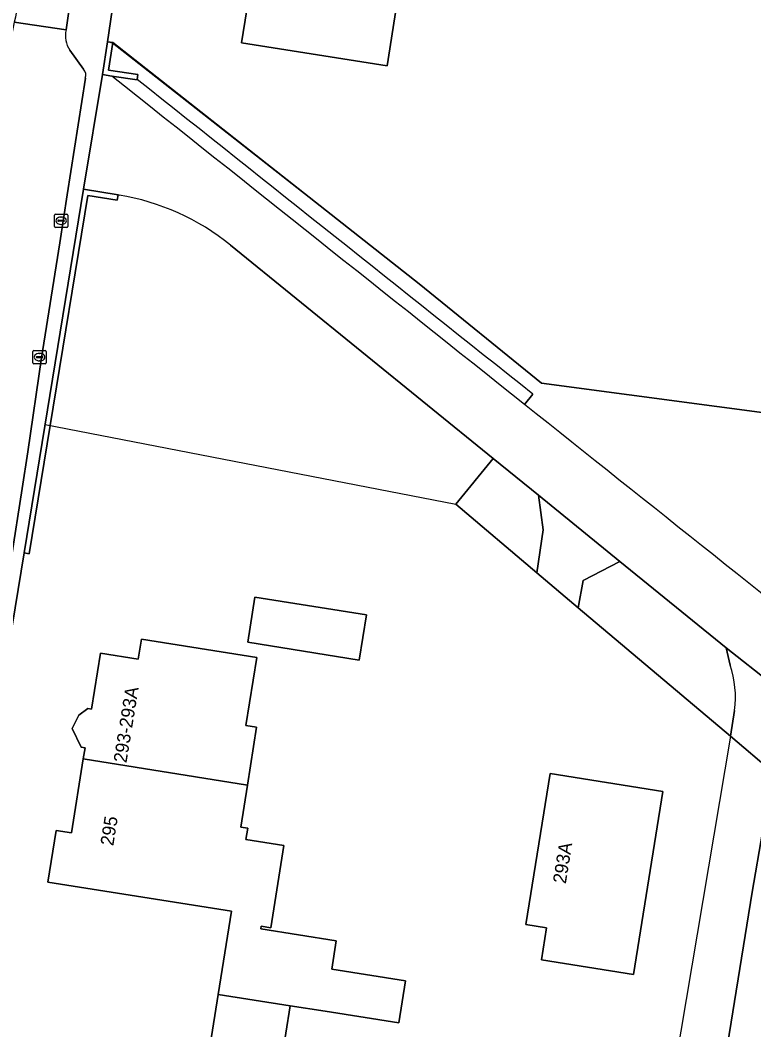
# Model space of a CAD drawing. Extents: x 161483 to 162250, y 379484 to 380833.
# Drawn here: x 161643 to 161698.5, y 380331.9 to 380408.4 of the extents above; entities that cross this region are included whole.
import ezdxf

# ---------------------------------------------------------------- set-up
doc = ezdxf.new("R2010")
doc.units = 0
for name, color, linetype in [('IMGEO_Berm_open', 7, 'Continuous'), ('IMGEO_Erf', 7, 'Continuous'), ('IMGEO_Gemengd_bos', 7, 'Continuous'), ('IMGEO_Groenvoorziening', 7, 'Continuous'), ('IMGEO_Hek', 7, 'Continuous'), ('IMGEO_Kolk', 7, 'Continuous'), ('IMGEO_Muur', 7, 'Continuous'), ('IMGEO_Pand', 7, 'Continuous'), ('IMGEO_Pand_nummerreeks', 7, 'Continuous'), ('IMGEO_Rijbaan_lokaal_gesloten', 7, 'Continuous'), ('IMGEO_Rijbaan_lokaal_open', 7, 'Continuous'), ('IMGEO_Voetpad_open', 7, 'Continuous')]:
    doc.layers.add(name, color=color, linetype=linetype)

msp = doc.modelspace()

# ---------------------------------------------------------------- linework, layer by layer
at = {"layer": 'IMGEO_Berm_open'}
for points in [[(161651.858, 380403.89), (161651.854, 380403.861), (161649.925, 380404.15)], [(161681.166, 380379.288), (161681.796, 380380.064)]]:
    msp.add_lwpolyline(points, dxfattribs=at)
for centre, radius, start, end in [((138294.945, 351024.776), 37531.357, 51.4562869, 51.517239), ((138866.822, 351743.167), 36614.135, 51.4557191, 51.5155932)]:
    msp.add_arc(centre, radius, start, end, dxfattribs=at)
at = {"layer": 'IMGEO_Erf'}
for points in [[(161655.481, 380444.917), (161652.656, 380427.511), (161649.605, 380406.735), (161650.001, 380406.676), (161673.199, 380388.404), (161682.464, 380380.888), (161735.153, 380373.873), (161748.237, 380371.945), (161806.448, 380361.939)], [(161650.485, 380395.132), (161650.417, 380395.143), (161650.352, 380394.748), (161648.132, 380395.111), (161645.281, 380377.689), (161643.693, 380367.982), (161643.298, 380368.047), (161641.71, 380358.328), (161639.778, 380345.223), (161639.349, 380342.516), (161637.808, 380332.784), (161635.369, 380317.381), (161635.308, 380316.997), (161633.936, 380308.445), (161631.258, 380291.759), (161630.498, 380287.027), (161630.411, 380286.482), (161629.564, 380286.608), (161620.762, 380287.923), (161620.152, 380288.014)], [(161689.432, 380260.789), (161685.342, 380261.452), (161698.403, 380342.353), (161699.96, 380351.452), (161696.758, 380354.158), (161685.238, 380363.892), (161682.099, 380366.545), (161675.967, 380371.726), (161678.79, 380375.2), (161658.93, 380391.337)], [(161657.125, 380329.22), (161657.983, 380334.622), (161658.983, 380340.917), (161645.099, 380343.122), (161645.72, 380347.032), (161646.887, 380346.847), (161647.778, 380352.459), (161647.909, 380353.281), (161647.617, 380353.327), (161646.945, 380354.759), (161647.435, 380355.751), (161648.133, 380356.258), (161648.399, 380356.215), (161649.072, 380360.454), (161651.942, 380359.998), (161652.182, 380361.51), (161660.909, 380360.124), (161660.091, 380354.971), (161660.896, 380354.843), (161660.201, 380350.464), (161659.697, 380347.291), (161660.225, 380347.207), (161660.088, 380346.345), (161662.958, 380345.889), (161661.969, 380339.659), (161661.25, 380339.773), (161661.217, 380339.569), (161666.918, 380338.663), (161666.58, 380336.538), (161672.165, 380335.65), (161671.657, 380332.452), (161666.072, 380333.341), (161663.439, 380333.76), (161662.78, 380329.612)]]:
    msp.add_lwpolyline(points, dxfattribs=at)
for points in [[(161659.762, 380406.657), (161660.426, 380410.915), (161657.166, 380411.427), (161657.742, 380415.123), (161653.474, 380415.793), (161656.362, 380434.33), (161660.63, 380433.66), (161661.201, 380437.326), (161669.312, 380436.052), (161669.286, 380435.884), (161673.079, 380435.288), (161673.222, 380436.207), (161683.16, 380434.647), (161680.52, 380417.701), (161672.617, 380418.942), (161671.761, 380413.448), (161669.967, 380413.73), (161669.736, 380412.227), (161671.873, 380411.891), (161670.787, 380404.925)], [(161668.669, 380359.934), (161660.226, 380361.275), (161660.769, 380364.692), (161669.212, 380363.351)], [(161682.462, 380337.234), (161682.848, 380339.651), (161681.278, 380339.901), (161683.104, 380351.337), (161691.634, 380349.975), (161689.423, 380336.122)]]:
    msp.add_lwpolyline(points, close=True, dxfattribs=at)
msp.add_arc((161647.577, 380377.367), 18.002, 50.90046, 80.70331, dxfattribs=at)
at = {"layer": 'IMGEO_Gemengd_bos'}
for points in [[(161864.627, 380322.421), (161873.896, 380332.874), (161892.434, 380327.721), (161912.955, 380319.175), (161938.555, 380308.279), (161970.776, 380294.439), (161977.443, 380290.655), (161980.656, 380286.401), (161988.72, 380322.899), (161905.254, 380342.685), (161850.183, 380353.545), (161841.256, 380355.187), (161823.962, 380358.713), (161806.448, 380361.939), (161748.237, 380371.945), (161735.153, 380373.873), (161682.464, 380380.888), (161673.199, 380388.404), (161650.001, 380406.676), (161649.688, 380404.59), (161651.913, 380404.256), (161651.858, 380403.89)], [(161681.796, 380380.064), (161681.166, 380379.288)], [(161700.442, 380354.267), (161699.96, 380351.452), (161698.403, 380342.353), (161685.342, 380261.452), (161689.432, 380260.789), (161686.003, 380233.366), (161688.203, 380233.083), (161695.69, 380232.106), (161686.731, 380176.657), (161700.345, 380174.454), (161695.053, 380163.494)]]:
    msp.add_lwpolyline(points, dxfattribs=at)
for centre, radius, start, end in [((138866.822, 351743.167), 36614.135, 51.4557191, 51.5155932), ((137738.126, 350325.622), 38425.148, 51.3474082, 51.4565018)]:
    msp.add_arc(centre, radius, start, end, dxfattribs=at)
at = {"layer": 'IMGEO_Groenvoorziening'}
msp.add_lwpolyline([(161682.224, 380372.409), (161678.79, 380375.2), (161675.967, 380371.726), (161682.099, 380366.545), (161682.574, 380369.795)], close=True, dxfattribs=at)
for points in [[(161688.397, 380367.393), (161685.623, 380365.954), (161685.238, 380363.892), (161696.758, 380354.158), (161697.06, 380356.122)], [(161696.729, 380359.556), (161696.429, 380360.867), (161688.397, 380367.393)]]:
    msp.add_lwpolyline(points, dxfattribs=at)
msp.add_arc((161689.957, 380357.17), 7.18, 351.60433, 19.40702, dxfattribs=at)
at = {"layer": 'IMGEO_Hek'}
for points in [[(161980.656, 380286.401), (161988.72, 380322.899), (161905.254, 380342.685), (161850.183, 380353.545), (161841.256, 380355.187), (161823.962, 380358.713), (161806.448, 380361.939), (161748.237, 380371.945), (161735.153, 380373.873), (161682.464, 380380.888), (161673.199, 380388.404), (161650, 380406.631), (161649.605, 380406.735)], [(161644.887, 380377.766), (161675.967, 380371.726), (161696.758, 380354.158), (161692.566, 380329.29)]]:
    msp.add_lwpolyline(points, dxfattribs=at)
at = {"layer": 'IMGEO_Kolk'}
for p, q in [((161645.6, 380392.766), (161645.6, 380393.618)), ((161645.675, 380393.692), (161646.527, 380393.692)), ((161645.859, 380393.186), (161645.859, 380393.198)), ((161645.902, 380393.235), (161646.3, 380393.235)), ((161646.088, 380393.472), (161646.113, 380393.472)), ((161646.343, 380393.198), (161646.343, 380393.186)), ((161646.601, 380393.618), (161646.601, 380392.766)), ((161646.527, 380392.692), (161645.675, 380392.692)), ((161646.297, 380393.149), (161645.899, 380393.149)), ((161646.111, 380392.912), (161646.086, 380392.912)), ((161643.969, 380382.44), (161643.969, 380383.292)), ((161644.044, 380383.366), (161644.896, 380383.366)), ((161644.97, 380383.292), (161644.97, 380382.44)), ((161644.228, 380382.86), (161644.228, 380382.872)), ((161644.666, 380382.823), (161644.268, 380382.823)), ((161644.271, 380382.909), (161644.669, 380382.909)), ((161644.48, 380382.586), (161644.455, 380382.586)), ((161644.457, 380383.146), (161644.482, 380383.146)), ((161644.712, 380382.872), (161644.712, 380382.86)), ((161644.896, 380382.366), (161644.044, 380382.366))]:
    msp.add_line(p, q, dxfattribs=at)
for points in [[(161645.6, 380392.766), (161645.6, 380393.618)], [(161645.675, 380393.692), (161646.527, 380393.692)], [(161646.601, 380393.618), (161646.601, 380392.766)], [(161646.527, 380392.692), (161645.675, 380392.692)], [(161643.969, 380382.44), (161643.969, 380383.292)], [(161644.044, 380383.366), (161644.896, 380383.366)], [(161644.97, 380383.292), (161644.97, 380382.44)], [(161644.896, 380382.366), (161644.044, 380382.366)]]:
    msp.add_lwpolyline(points, dxfattribs=at)
for centre, radius, start, end in [((161645.677, 380393.616), 0.0765, 91.55205, 178.44795), ((161645.677, 380393.616), 0.0765, 91.55205, 178.44795), ((161645.899, 380393.195), 0.0403, 85.87752, 175.75265), ((161645.896, 380393.185), 0.0366, 178.93798, 274.71019), ((161646.3, 380393.192), 0.043, 264.86636, 352.45326), ((161646.304, 380393.197), 0.0386, 1.73085, 96.63898), ((161646.525, 380393.616), 0.0765, 1.55205, 88.44795), ((161646.525, 380393.616), 0.0765, 1.55205, 88.44795), ((161645.677, 380392.768), 0.0765, 181.55205, 268.44795), ((161645.677, 380392.768), 0.0765, 181.55205, 268.44795), ((161646.525, 380392.768), 0.0765, 271.55205, 358.44795), ((161646.525, 380392.768), 0.0765, 271.55205, 358.44795), ((161644.046, 380383.29), 0.0765, 91.55205, 178.44795), ((161644.046, 380383.29), 0.0765, 91.55205, 178.44795), ((161644.894, 380383.29), 0.0765, 1.55205, 88.44795), ((161644.894, 380383.29), 0.0765, 1.55205, 88.44795), ((161644.268, 380382.869), 0.0403, 85.87752, 175.75265), ((161644.265, 380382.859), 0.0366, 178.93798, 274.71019), ((161644.669, 380382.866), 0.043, 264.86636, 352.45326), ((161644.673, 380382.871), 0.0386, 1.73085, 96.63898), ((161644.046, 380382.442), 0.0765, 181.55205, 268.44795), ((161644.046, 380382.442), 0.0765, 181.55205, 268.44795), ((161644.894, 380382.442), 0.0765, 271.55205, 358.44795), ((161644.894, 380382.442), 0.0765, 271.55205, 358.44795)]:
    msp.add_arc(centre, radius, start, end, dxfattribs=at)
for centre, major_axis, ratio, start_param, end_param in [((161646.087, 380393.192), (-0.387, 0.002), 0.722429, 4.712389, 7.853982), ((161646.112, 380393.192), (-0.39, 0.002), 0.717154, 1.570796, 4.712389), ((161644.456, 380382.866), (-0.387, 0.002), 0.722429, 4.712389, 7.853982), ((161644.481, 380382.866), (-0.39, 0.002), 0.717154, 1.570796, 4.712389)]:
    msp.add_ellipse(centre, major_axis=major_axis, ratio=ratio, start_param=start_param, end_param=end_param, dxfattribs=at)
at = {"layer": 'IMGEO_Muur'}
for points in [[(161650.001, 380406.676), (161649.605, 380406.735), (161649.233, 380404.254), (161649.925, 380404.15), (161651.854, 380403.861), (161651.858, 380403.89), (161651.913, 380404.256), (161649.688, 380404.59)], [(161650.417, 380395.143), (161647.801, 380395.571), (161643.298, 380368.047), (161643.693, 380367.982), (161645.281, 380377.689), (161648.132, 380395.111), (161650.352, 380394.748)]]:
    msp.add_lwpolyline(points, close=True, dxfattribs=at)
at = {"layer": 'IMGEO_Pand'}
for points in [[(161670.787, 380404.925), (161671.873, 380411.891), (161669.736, 380412.227), (161669.967, 380413.73), (161671.761, 380413.448), (161672.617, 380418.942), (161680.52, 380417.701), (161683.16, 380434.647), (161673.222, 380436.207), (161673.079, 380435.288), (161669.286, 380435.884), (161669.312, 380436.052), (161661.201, 380437.326), (161660.63, 380433.66), (161656.362, 380434.33), (161653.474, 380415.793), (161657.742, 380415.123), (161657.166, 380411.427), (161660.426, 380410.915), (161659.762, 380406.657)], [(161668.669, 380359.934), (161669.212, 380363.351), (161660.769, 380364.692), (161660.226, 380361.275)], [(161660.201, 380350.464), (161660.896, 380354.843), (161660.091, 380354.971), (161660.909, 380360.124), (161652.182, 380361.51), (161651.942, 380359.998), (161649.072, 380360.454), (161648.399, 380356.215), (161648.133, 380356.258), (161647.435, 380355.751), (161646.945, 380354.759), (161647.617, 380353.327), (161647.909, 380353.281), (161647.778, 380352.459)], [(161662.958, 380345.889), (161660.088, 380346.345), (161660.225, 380347.207), (161659.697, 380347.291), (161660.201, 380350.464), (161647.778, 380352.459), (161646.887, 380346.847), (161645.72, 380347.032), (161645.099, 380343.122), (161658.983, 380340.917), (161657.983, 380334.622), (161663.439, 380333.76), (161666.072, 380333.341), (161671.657, 380332.452), (161672.165, 380335.65), (161666.58, 380336.538), (161666.918, 380338.663), (161661.217, 380339.569), (161661.25, 380339.773), (161661.969, 380339.659)], [(161691.634, 380349.975), (161683.104, 380351.337), (161681.278, 380339.901), (161682.848, 380339.651), (161682.462, 380337.234), (161689.423, 380336.122)]]:
    msp.add_lwpolyline(points, close=True, dxfattribs=at)
msp.add_lwpolyline([(161645.778, 380328.593), (161645.116, 380324.423), (161655.816, 380322.745), (161656.386, 380326.334), (161656.98, 380326.24), (161657.446, 380329.173), (161659.272, 380328.883), (161662.58, 380328.357), (161662.78, 380329.612), (161663.439, 380333.76), (161657.983, 380334.622), (161657.125, 380329.22), (161655.77, 380329.435), (161655.873, 380330.084), (161650.364, 380330.829), (161650.281, 380330.308), (161648.46, 380330.597)], dxfattribs=at)
at = {"layer": 'IMGEO_Rijbaan_lokaal_gesloten'}
for points in [[(161649.925, 380404.15), (161649.233, 380404.254), (161647.801, 380395.571), (161650.417, 380395.143), (161650.485, 380395.132)], [(161658.93, 380391.337), (161678.79, 380375.2), (161682.224, 380372.409), (161688.397, 380367.393), (161696.429, 380360.867), (161703.348, 380355.396), (161735.485, 380330.022), (161738.346, 380333.645)]]:
    msp.add_lwpolyline(points, dxfattribs=at)
for centre, radius, start, end in [((138294.945, 351024.776), 37531.357, 51.4562869, 51.517239), ((161647.577, 380377.367), 18.002, 50.90046, 80.70331), ((137738.126, 350325.622), 38425.148, 51.3474082, 51.4565018)]:
    msp.add_arc(centre, radius, start, end, dxfattribs=at)
at = {"layer": 'IMGEO_Rijbaan_lokaal_open'}
for points in [[(161646.94, 380410.827), (161643.106, 380411.379), (161642.658, 380408.596), (161642.538, 380408.239), (161646.482, 380407.658)], [(161682.224, 380372.409), (161682.574, 380369.795), (161682.099, 380366.545), (161685.238, 380363.892), (161685.623, 380365.954), (161688.397, 380367.393)]]:
    msp.add_lwpolyline(points, close=True, dxfattribs=at)
for points in [[(161646.482, 380407.658), (161642.538, 380408.239), (161642.386, 380407.459), (161639.769, 380391.031)], [(161647.802, 380404.665), (161646.764, 380406.104)], [(161640.378, 380355.291), (161641.46, 380362.225), (161643.156, 380372.92), (161643.576, 380375.703), (161644.625, 380382.821), (161646.006, 380391.519), (161646.561, 380395.161), (161647.932, 380403.996)], [(161696.429, 380360.867), (161696.729, 380359.556)], [(161703.348, 380355.396), (161696.429, 380360.867)], [(161697.06, 380356.122), (161696.758, 380354.158), (161699.96, 380351.452), (161700.442, 380354.267)]]:
    msp.add_lwpolyline(points, dxfattribs=at)
for centre, radius, start, end in [((161648.315, 380407.188), 1.892, 165.62138, 214.94937), ((161647.328, 380404.226), 0.646, 339.15014, 42.84319), ((161689.957, 380357.17), 7.18, 351.60433, 19.40702)]:
    msp.add_arc(centre, radius, start, end, dxfattribs=at)
at = {"layer": 'IMGEO_Voetpad_open'}
for points in [[(161647.801, 380395.571), (161649.233, 380404.254), (161649.605, 380406.735), (161652.656, 380427.511), (161655.481, 380444.917)], [(161646.956, 380410.929), (161646.94, 380410.827), (161646.482, 380407.658)], [(161646.764, 380406.104), (161647.802, 380404.665)], [(161647.932, 380403.996), (161646.561, 380395.161), (161646.006, 380391.519), (161644.625, 380382.821), (161643.576, 380375.703), (161643.156, 380372.92), (161641.46, 380362.225), (161640.378, 380355.291), (161638.736, 380345.42), (161638.284, 380342.702), (161639.349, 380342.516), (161639.778, 380345.223), (161641.71, 380358.328), (161643.298, 380368.047), (161647.801, 380395.571)]]:
    msp.add_lwpolyline(points, dxfattribs=at)
for centre, radius, start, end in [((161648.315, 380407.188), 1.892, 165.62138, 214.94937), ((161647.328, 380404.226), 0.646, 339.15014, 42.84319)]:
    msp.add_arc(centre, radius, start, end, dxfattribs=at)

# ---------------------------------------------------------------- texts
at = {"layer": 'IMGEO_Pand_nummerreeks'}
for s, rotation, p in [('293-293A', 80.80634, (161651.043, 380352.104)), ('295', 80.97613, (161650.046, 380345.822)), ('293A', 80.93029, (161684.298, 380342.959))]:
    msp.add_text(s, height=1, rotation=rotation, dxfattribs=at).set_placement(p)

doc.saveas('drawing.dxf')
